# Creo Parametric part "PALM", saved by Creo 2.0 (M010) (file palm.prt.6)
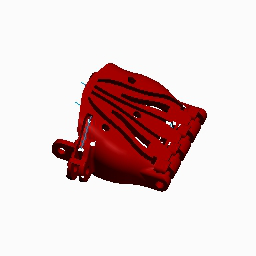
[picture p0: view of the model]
Units: Inch lbm Second (Pro/E Default); INCH, POUND, SECS

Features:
  1. datum plane "RIGHT"
  2. datum plane "TOP"
  3. datum plane "FRONT"
  4. coordinate system
  5. curve "Sketch 1"
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
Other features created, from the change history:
  extruded cut "Extrude 24"
  round "Round 13"
  sketch "Sketch 32"
  extruded cut "Extrude 25"
  round "Round 14"
  round "Round 15"
  sketch "Sketch 33"
  extruded cut "Extrude 26" (2 times)
  sketch "Sketch 34"
  swept cut "Sweep 2"
  sketch "Sketch 35"
  datum plane "DTM7"
  sketch "Sketch 36"
  swept cut "Sweep 3" (2 times)
  round "Round 16" (2 times)
  round "Round 17"
  sketch "Sketch 37"
  extruded cut "Extrude 27"
  sketch "Sketch 38"
  extrusion "Extrude 28"

Other named items: KNUCKLEBASEBLOCK, FINGERJOINTSLOTS, FINGERPIN, WRISTJOINT_PIN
